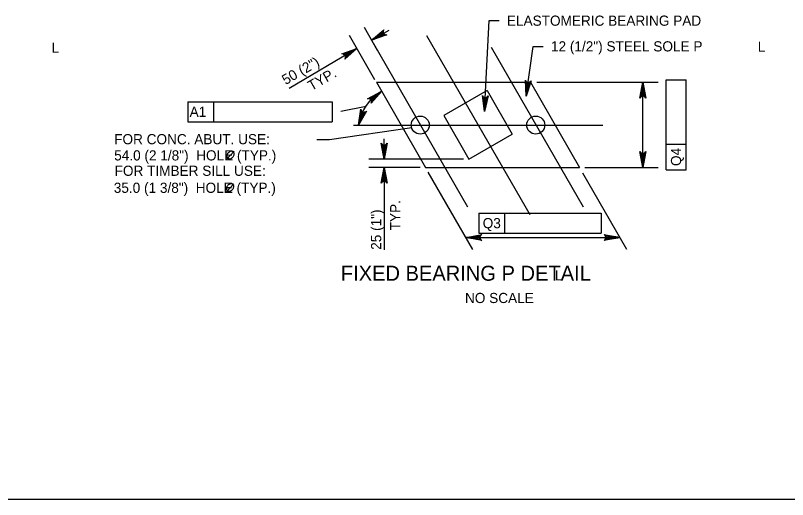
# Model space of a CAD drawing. Extents: x 638263 to 640360, y 293683 to 298655.
# Drawn here: x 638729.9 to 638957.6, y 294886.5 to 295029.3 of the extents above; entities that cross this region are included whole.
import ezdxf

# ---------------------------------------------------------------- set-up
doc = ezdxf.new("R2010")
doc.units = 0
for name, color, linetype in [('2', 7, 'Continuous'), ('3', 7, 'Continuous'), ('4', 7, 'Continuous')]:
    doc.layers.add(name, color=color, linetype=linetype)

msp = doc.modelspace()

# ---------------------------------------------------------------- linework, layer by layer
at = {"layer": '2'}
msp.add_line((639261.46, 294886.46), (638475.46, 294886.46), dxfattribs=at)
at = {"layer": '3'}
for p, q in [((638851.11, 295023.36), (638881.52, 294970.56)), ((638835.43, 295021.07), (638863.2, 294972.84)), ((638870.13, 295019.98), (638897.27, 294972.84)), ((638836.35, 295009.6), (638881.71, 295009.6)), ((638836.35, 295009.6), (638850.83, 294984.47)), ((638881.71, 295009.6), (638896.18, 294984.47)), ((638869, 295007.14), (638856.21, 294999.77)), ((638869, 295007.14), (638876.4, 294994.3)), ((638856.21, 294999.77), (638863.61, 294986.93)), ((638863.61, 294986.93), (638876.4, 294994.3)), ((638850.83, 294984.47), (638896.18, 294984.47))]:
    msp.add_line(p, q, dxfattribs=at)
for points in [[(638880.44, 295005.52), (638880.24, 295010.26), (638880.43, 295009.86), (638880.72, 295009.64), (638881.02, 295009.54), (638881.34, 295009.55), (638881.67, 295009.69), (638881.97, 295010.01), (638880.44, 295005.52), (638881.67, 295009.69), (638881.34, 295009.55), (638880.44, 295005.52), (638881.02, 295009.54), (638880.72, 295009.64), (638880.44, 295005.52), (638880.43, 295009.86)], [(638914.89, 295009.6), (638915.76, 295004.94), (638915.51, 295005.3), (638915.2, 295005.48), (638914.89, 295005.54), (638914.57, 295005.48), (638914.26, 295005.3), (638914.01, 295004.94), (638914.89, 295009.6), (638914.26, 295005.3), (638914.57, 295005.48), (638914.89, 295009.6), (638914.89, 295005.54), (638915.2, 295005.48), (638914.89, 295009.6), (638915.51, 295005.3)], [(638837.87, 295006.96), (638834.76, 295003.38), (638834.89, 295003.8), (638834.84, 295004.16), (638834.69, 295004.44), (638834.45, 295004.65), (638834.12, 295004.78), (638833.68, 295004.75), (638837.87, 295006.96), (638834.12, 295004.78), (638834.45, 295004.65), (638837.87, 295006.96), (638834.69, 295004.44), (638834.84, 295004.16), (638837.87, 295006.96), (638834.89, 295003.8)], [(638868.21, 295000.99), (638867.57, 295005.69), (638867.8, 295005.32), (638868.1, 295005.12), (638868.41, 295005.05), (638868.73, 295005.09), (638869.05, 295005.26), (638869.31, 295005.6), (638868.21, 295000.99), (638869.05, 295005.26), (638868.73, 295005.09), (638868.21, 295000.99), (638868.41, 295005.05), (638868.1, 295005.12), (638868.21, 295000.99), (638867.8, 295005.32)], [(638831.02, 294996.96), (638831.74, 295001.64), (638831.86, 295001.22), (638832.09, 295000.94), (638832.37, 295000.79), (638832.68, 295000.74), (638833.04, 295000.81), (638833.39, 295001.06), (638831.02, 294996.96), (638833.04, 295000.81), (638832.68, 295000.74), (638831.02, 294996.96), (638832.37, 295000.79), (638832.09, 295000.94), (638831.02, 294996.96), (638831.86, 295001.22)], [(638838.61, 294986.93), (638837.74, 294991.59), (638837.98, 294991.23), (638838.3, 294991.05), (638838.61, 294990.99), (638838.92, 294991.05), (638839.23, 294991.23), (638839.48, 294991.59), (638838.61, 294986.93), (638839.23, 294991.23), (638838.92, 294991.05), (638838.61, 294986.93), (638838.61, 294990.99), (638838.3, 294991.05), (638838.61, 294986.93), (638837.98, 294991.23)], [(638914.89, 294984.47), (638914.01, 294989.13), (638914.26, 294988.77), (638914.57, 294988.59), (638914.89, 294988.53), (638915.2, 294988.59), (638915.51, 294988.77), (638915.76, 294989.13), (638914.89, 294984.47), (638915.51, 294988.77), (638915.2, 294988.59), (638914.89, 294984.47), (638914.89, 294988.53), (638914.57, 294988.59), (638914.89, 294984.47), (638914.26, 294988.77)], [(638838.61, 294984.47), (638839.48, 294979.81), (638839.23, 294980.17), (638838.92, 294980.35), (638838.61, 294980.41), (638838.3, 294980.35), (638837.98, 294980.17), (638837.74, 294979.81), (638838.61, 294984.47), (638837.98, 294980.17), (638838.3, 294980.35), (638838.61, 294984.47), (638838.61, 294980.41), (638838.92, 294980.35), (638838.61, 294984.47), (638839.23, 294980.17)], [(638862.74, 294963.77), (638867.4, 294964.65), (638867.05, 294964.4), (638866.86, 294964.09), (638866.81, 294963.77), (638866.86, 294963.46), (638867.05, 294963.15), (638867.4, 294962.9), (638862.74, 294963.77), (638867.05, 294963.15), (638866.86, 294963.46), (638862.74, 294963.77), (638866.81, 294963.77), (638866.86, 294964.09), (638862.74, 294963.77), (638867.05, 294964.4)], [(638908.1, 294963.77), (638903.44, 294962.9), (638903.8, 294963.15), (638903.98, 294963.46), (638904.04, 294963.77), (638903.98, 294964.09), (638903.8, 294964.4), (638903.44, 294964.65), (638908.1, 294963.77), (638903.8, 294964.4), (638903.98, 294964.09), (638908.1, 294963.77), (638904.04, 294963.77), (638903.98, 294963.46), (638908.1, 294963.77), (638903.8, 294963.15)]]:
    msp.add_lwpolyline(points, dxfattribs=at)
for centre in [(638849.24, 294996.95), (638883.31, 294996.95)]:
    msp.add_circle(centre, 2.66, dxfattribs=at)
at = {"layer": '4'}
for p, q in [((638836.65, 295018.94), (638832.77, 295025.78)), ((638868.21, 295000.99), (638869.55, 295027.77)), ((638869.55, 295027.77), (638872.55, 295027.77)), ((638835.84, 295010.32), (638828.39, 295023.43)), ((638834.91, 295022), (638840.1, 295024.98)), ((638830.59, 295019.55), (638810.55, 295007.75)), ((638880.44, 295005.52), (638882.54, 295020.19)), ((638882.54, 295020.19), (638885.54, 295020.19)), ((638921.72, 295010.32), (638927.62, 295010.32)), ((638921.72, 294991.33), (638921.72, 295010.32)), ((638927.62, 294983.77), (638927.62, 295010.32)), ((638883.66, 295009.6), (638919.39, 295009.6)), ((638914.89, 294984.47), (638914.89, 295009.6)), ((638780.73, 295003.84), (638788.29, 295003.84)), ((638780.73, 295003.84), (638780.73, 294997.93)), ((638788.29, 295003.84), (638788.29, 294997.93)), ((638788.29, 295003.84), (638823.25, 295003.84)), ((638823.25, 295003.84), (638823.25, 294997.93)), ((638833.3, 295002.48), (638825.8, 295000.98)), ((638780.73, 294997.93), (638823.25, 294997.93)), ((638846.72, 294996.13), (638822.48, 294992.61)), ((638829.57, 294996.96), (638903.06, 294996.96)), ((638822.48, 294992.61), (638818.79, 294992.61)), ((638838.61, 294986.93), (638838.61, 294992.93)), ((638792.14, 294986.82), (638794.38, 294989.27)), ((638921.72, 294983.77), (638921.72, 294991.33)), ((638921.72, 294991.33), (638927.62, 294991.33)), ((638862.04, 294986.93), (638834.11, 294986.93)), ((638849.26, 294984.47), (638834.11, 294984.47)), ((638838.61, 294984.47), (638838.61, 294960.13)), ((638864.77, 294960.26), (638851.62, 294983.1)), ((638910.12, 294960.26), (638897.17, 294982.76)), ((638897.75, 294984.47), (638919.39, 294984.47)), ((638921.72, 294983.77), (638927.62, 294983.77)), ((638792.02, 294977.2), (638794.26, 294979.65)), ((638866.57, 294970.97), (638874.13, 294970.97)), ((638866.57, 294970.97), (638866.57, 294965.07)), ((638874.13, 294970.97), (638874.13, 294965.07)), ((638874.13, 294970.97), (638902.63, 294970.97)), ((638902.63, 294970.97), (638902.63, 294965.07)), ((638866.57, 294965.07), (638902.63, 294965.07)), ((638862.74, 294963.77), (638908.1, 294963.77))]:
    msp.add_line(p, q, dxfattribs=at)
for points in [[(638834.91, 295022), (638838.52, 295025.08), (638838.33, 295024.69), (638838.33, 295024.33), (638838.43, 295024.03), (638838.64, 295023.78), (638838.95, 295023.61), (638839.39, 295023.57), (638834.91, 295022), (638838.95, 295023.61), (638838.64, 295023.78), (638834.91, 295022), (638838.43, 295024.03), (638838.33, 295024.33), (638834.91, 295022), (638838.33, 295024.69)], [(638830.59, 295019.55), (638827.02, 295016.43), (638827.2, 295016.83), (638827.2, 295017.19), (638827.09, 295017.49), (638826.89, 295017.73), (638826.57, 295017.91), (638826.13, 295017.94), (638830.59, 295019.55), (638826.57, 295017.91), (638826.89, 295017.73), (638830.59, 295019.55), (638827.09, 295017.49), (638827.2, 295017.19), (638830.59, 295019.55), (638827.2, 295016.83)]]:
    msp.add_lwpolyline(points, dxfattribs=at)
for points in [[(638914.39, 295006.6), (638915.39, 295006.6), (638914.89, 295009.6)], [(638838.11, 294989.93), (638839.11, 294989.93), (638838.61, 294986.93)], [(638914.39, 294987.47), (638915.39, 294987.47), (638914.89, 294984.47)], [(638838.11, 294981.47), (638839.11, 294981.47), (638838.61, 294984.47)], [(638865.74, 294964.27), (638865.74, 294963.27), (638862.74, 294963.77)], [(638905.1, 294964.27), (638905.1, 294963.27), (638908.1, 294963.77)]]:
    msp.add_lwpolyline(points, close=True, dxfattribs=at)
msp.add_arc((638844.86, 294994.83), 14, 119.9358, 171.2534, dxfattribs=at)
for points in [[(638794.15, 294989.03), (638793.97, 294989.16), (638793.8, 294989.21), (638793.58, 294989.23), (638793.45, 294989.23), (638793.24, 294989.18), (638793.04, 294989.09), (638792.9, 294989.01), (638792.64, 294988.8), (638792.43, 294988.53), (638792.31, 294988.28), (638792.23, 294988.05), (638792.21, 294987.83), (638792.23, 294987.65), (638792.33, 294987.38), (638792.42, 294987.25), (638792.61, 294987.1), (638792.9, 294987.03), (638793.23, 294987.04), (638793.65, 294987.23), (638793.95, 294987.49), (638794.18, 294987.81), (638794.33, 294988.14), (638794.38, 294988.51), (638794.32, 294988.75), (638794.16, 294989.03)], [(638794.03, 294979.41), (638793.85, 294979.55), (638793.68, 294979.59), (638793.46, 294979.61), (638793.33, 294979.61), (638793.12, 294979.57), (638792.92, 294979.47), (638792.78, 294979.4), (638792.52, 294979.18), (638792.31, 294978.92), (638792.18, 294978.66), (638792.11, 294978.43), (638792.09, 294978.22), (638792.11, 294978.03), (638792.2, 294977.77), (638792.3, 294977.63), (638792.49, 294977.48), (638792.78, 294977.42), (638793.11, 294977.43), (638793.53, 294977.62), (638793.83, 294977.88), (638794.06, 294978.2), (638794.21, 294978.53), (638794.26, 294978.89), (638794.2, 294979.13), (638794.04, 294979.41)]]:
    msp.add_spline(points, degree=3, dxfattribs=at)

# ---------------------------------------------------------------- texts
for s, height, p in [('ELASTOMERIC BEARING PAD', 3, (638874.8, 295026.27)), ('L', 3, (638740.5, 295018.28)), ('12 (1/2") STEEL SOLE P', 3, (638887.79, 295018.69)), ('L', 3, (638948.77, 295018.61)), ('FOR CONC. ABUT. USE:', 3, (638758.99, 294991.3)), ('54.0 (2 1/8")  HOLE (TYP.)', 3, (638758.99, 294986.52)), ('FOR TIMBER SILL USE:', 3, (638759.11, 294981.98)), ('35.0 (1 3/8")  HOLE (TYP.)', 3, (638758.87, 294976.96)), ('FIXED BEARING P DETAIL', 4.4292, (638825.83, 294951.03)), ('L', 3, (638888.99, 294951.1)), ('NO SCALE', 3, (638862.44, 294944.44))]:
    msp.add_text(s, height=height, dxfattribs=at).set_placement(p)
for s, rotation, p in [('50 (2")', 29.9358, (638809.54, 295008.73)), ('TYP.', 29.9358, (638817.17, 295006.97)), ('A1', 359.9382, (638781.24, 294999.39)), ('Q4', 89.9382, (638926.17, 294984.87)), ('TYP.', 90, (638843.35, 294965.91)), ('25 (1")', 90, (638837.74, 294960.15)), ('Q3', 359.9382, (638867.66, 294966.52))]:
    msp.add_text(s, height=3, rotation=rotation, dxfattribs=at).set_placement(p)

doc.saveas('drawing.dxf')
